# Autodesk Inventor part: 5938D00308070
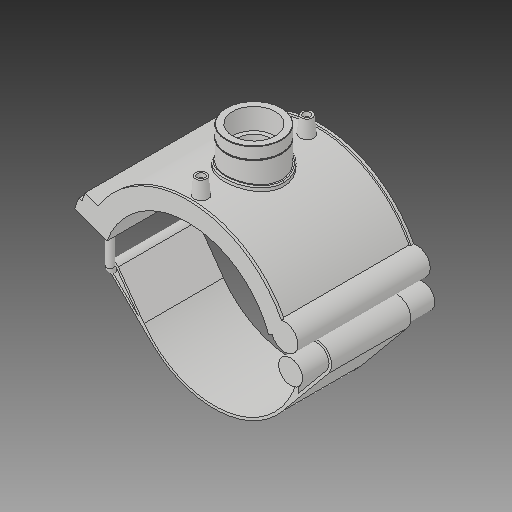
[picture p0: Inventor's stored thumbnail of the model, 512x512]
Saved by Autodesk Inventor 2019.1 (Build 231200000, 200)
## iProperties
Created: 2017-07
Part Number: 5938D00308070
Material: Generic
Description: PLASSON TRANSITION SADDLE 8''DIPS x 2"NPT
Document SubType Name: Modeling
Designer: KIM
Density: 1 g/cm^3
Appearance: Default
Author: KIM
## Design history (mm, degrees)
derived "5938D.ipt"
feature "Solid1::5938D.ipt"
tag "TaggingFeature1"
body "Solid1"
other parameters: "d0" = 228.9, "d1" = 274.68, "d2" = 449.58, "d3" = 57.225, "d4" = 176.022, "d5" = 0, "d40" = 142.8336, "d41" = 79.3184, "d43" = 0, "d45" = 0, "d47" = 184.076, "d48" = 73.6528, "d50" = 0, "d78" = 159.34, "d79" = 15, "d80" = 70.4088, "d82" = 5 deg, "d84" = 4, "d85" = 14, "d86" = 0, "d87" = 3, "d88" = 0, "d96" = 280.1736, "d97" = 3.52044, "d98" = 0, "d102" = 1.69968, "d103" = 56.656, "d104" = 28.0416, "d105" = 0, "d106" = 45.3248, "d108" = 0, "d109" = -15.57867, "d111" = 0.5, "d112" = 0.5, "d113" = 0, "d114" = 0.5, "d117" = 0.56656, "d120" = 140 deg, "d121" = 24.228, "d122" = 20 deg, "d123" = 1098.72, "d124" = 164.808, "d126" = 0, "d143" = 235.767, "d145" = 35.21538, "d149" = 3.4335, "d150" = 38.73692, "d153" = 176.022, "d154" = 0, "d156" = 137.34, "d157" = 160 deg, "d159" = 9.156, "d161" = 3.4335, "d162" = 105.6132, "d163" = 0, "d164" = 114.45, "d167" = 22.89, "d168" = 133.99024, "d170" = 3.4335, "d172" = 0, "d173" = 1, "d175" = 114.45, "d176" = 20 deg, "d177" = 16.023, "d178" = 45.78, "d180" = 0, "d183" = 18.312, "d184" = 12.8184, "d185" = 57.20715, "d186" = 57.20715, "d187" = 137.34, "d188" = 13.734, "d189" = 16.023, "d190" = 0, "d191" = 164.808, "d193" = 9.156, "d194" = 4.69245, "d195" = 90 deg, "d197" = 0, "d199" = 0, "d_" = 228.9, "B_" = 179.832, "H_" = 46.736, "L_" = 176.022, "d_t" = 6, "G_" = 56.656, "d148" = 3.4335, "d160" = 3.4335, "d169" = 3.4335, "d192" = 9.156
